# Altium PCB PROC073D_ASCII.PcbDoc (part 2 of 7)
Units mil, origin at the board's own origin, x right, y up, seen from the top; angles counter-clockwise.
Board outline 2165.35 x 2695.12 mil, 8 copper layers (Top Layer, L2_GND, L3_SIGNAL 1, L4_SIGNAL 2, L5_SIGNAL 3, L6_SIGNAL 4, L7_GND, Bottom Layer), stack 56.1 mil thick; 414 components, 319 nets, 1353 pads, 1669 vias.
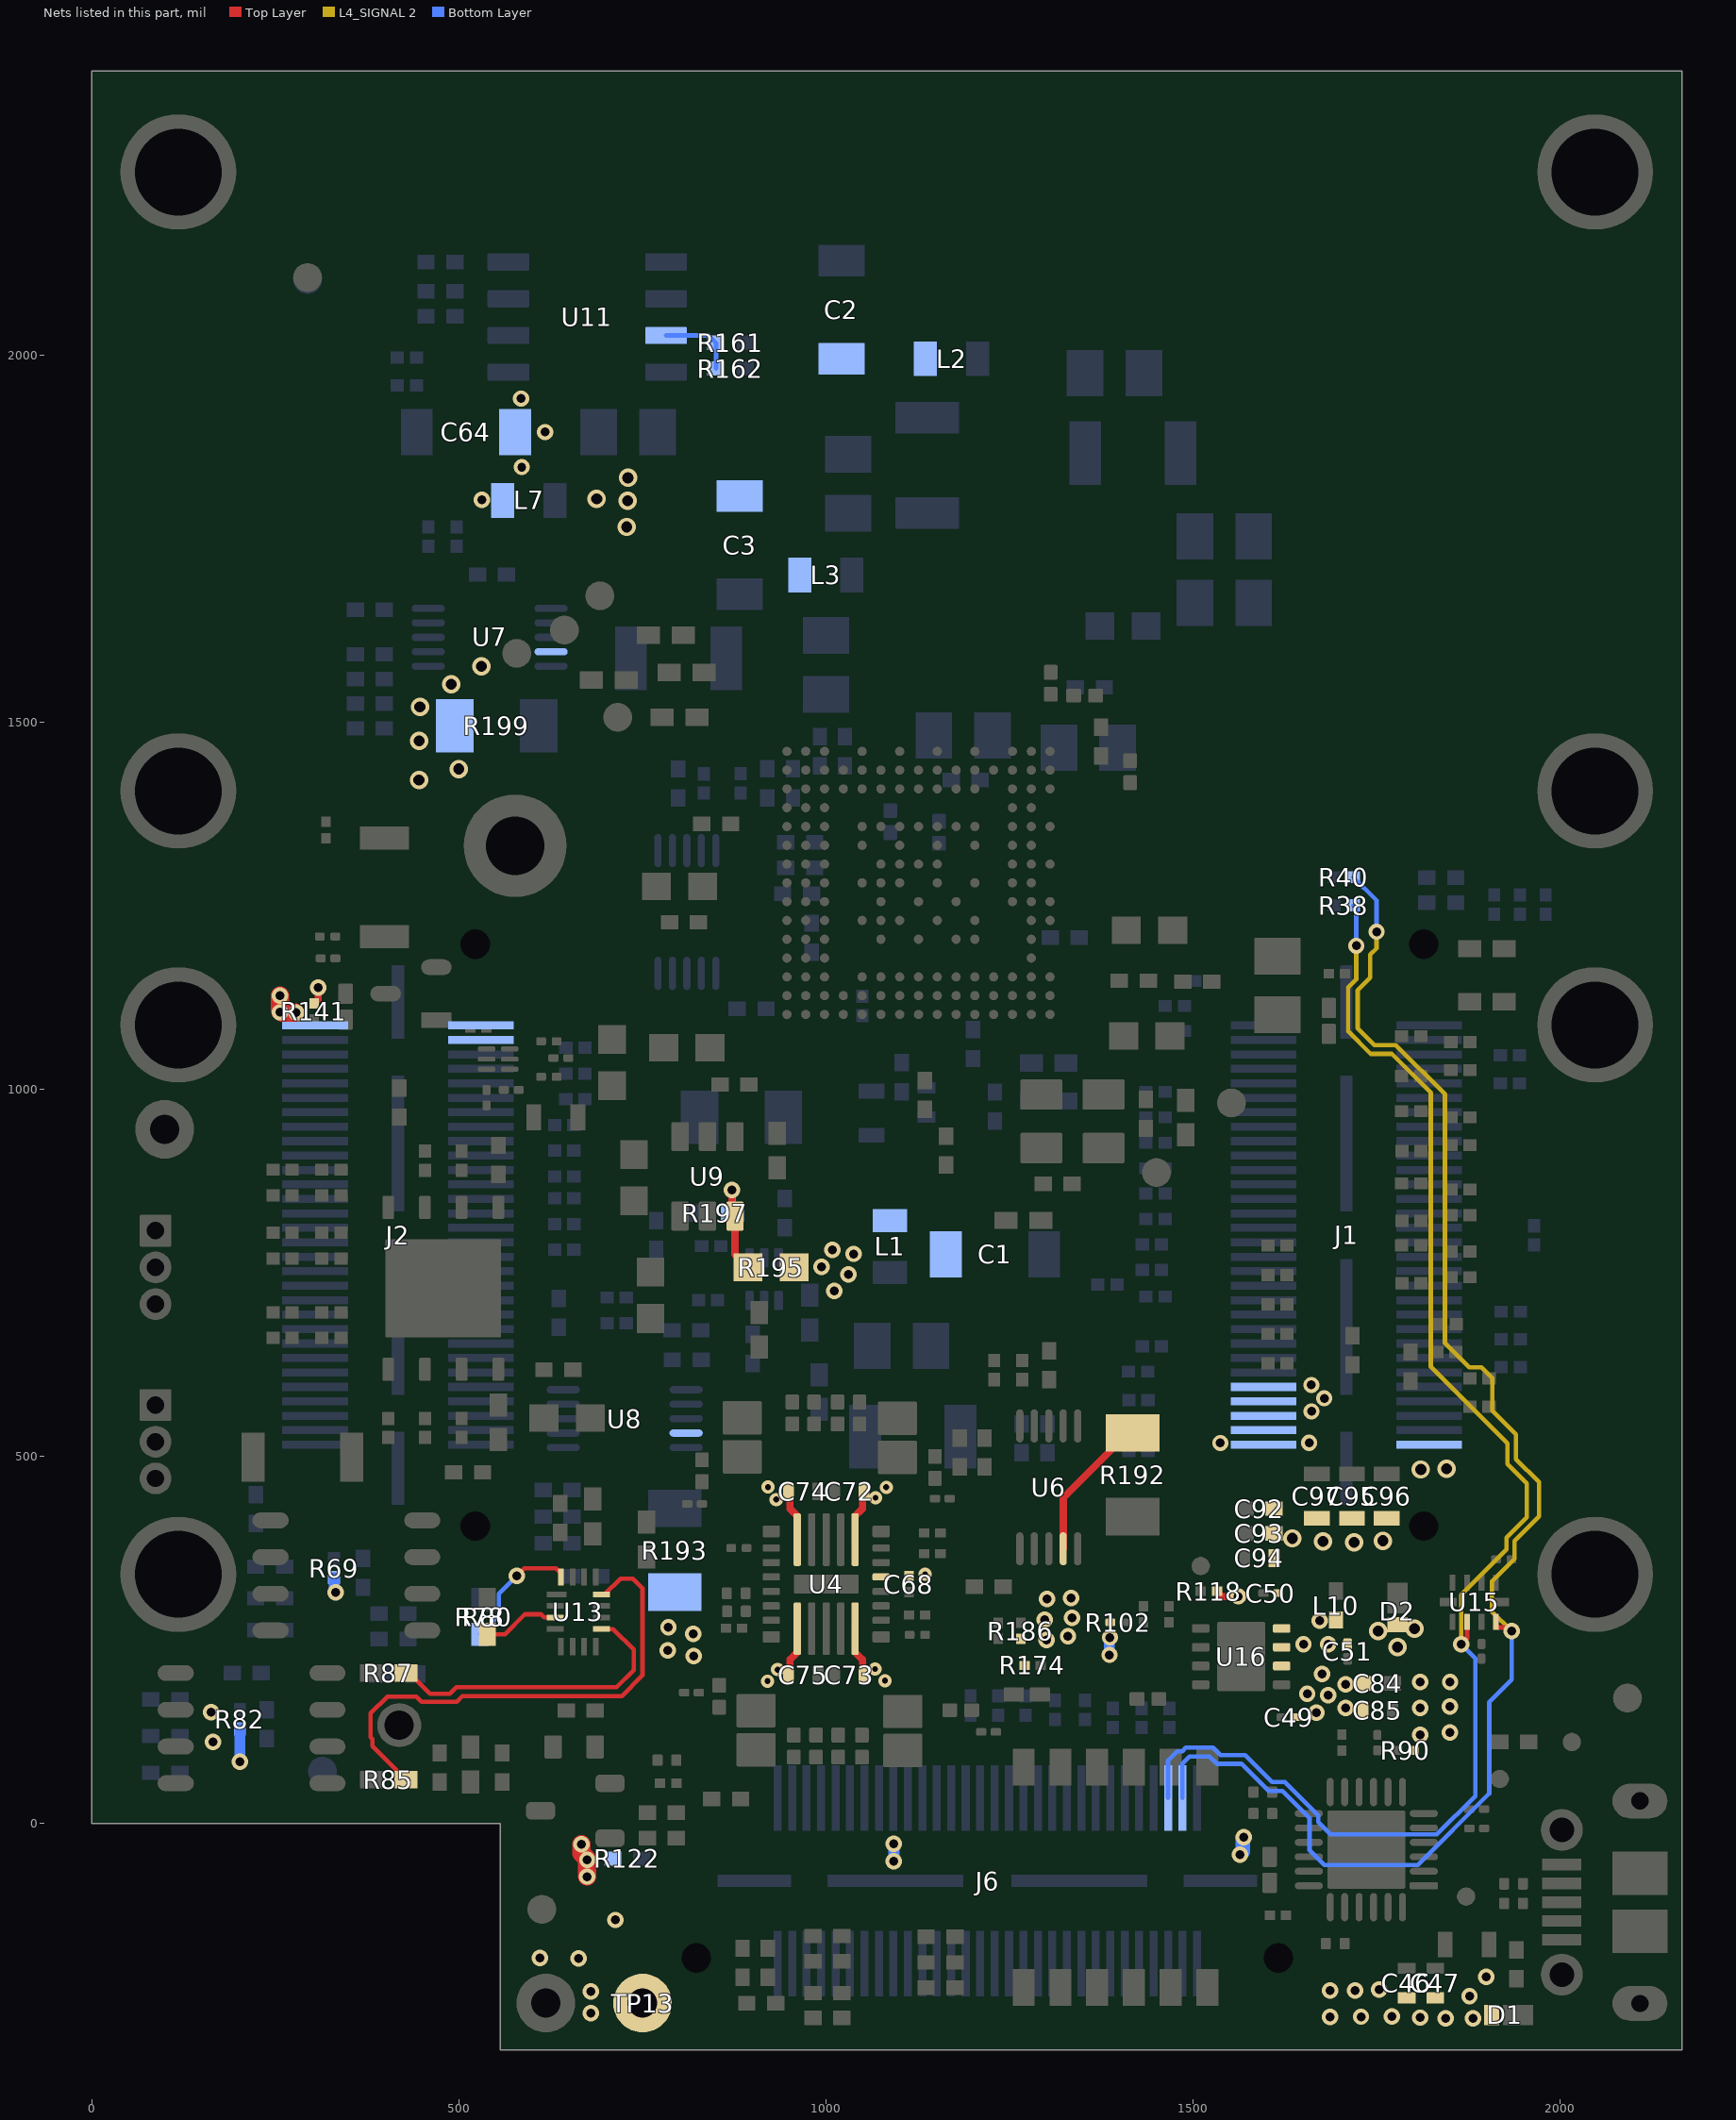
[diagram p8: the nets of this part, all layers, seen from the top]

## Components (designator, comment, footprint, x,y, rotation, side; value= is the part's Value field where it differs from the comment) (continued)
R152 "CRCW040210K0FKED" 0402L 1795.94,622.55 r90 top
R153 "CRCW0402100KFKED" 0402L 1837.89,1288.13 r0 bottom
R154 "CRCW0402100KFKED" 0402L 1837.89,1254.19 r0 bottom
R155 "CRCW0402100KFKED" 0402L 1717.01,644.6 r90 top
R156 "CRCW0402100KFKED" 0402L 1230,976.43 r90 bottom
R157 "CRCW040210K0FKED" 0402L 475,2052.43 r180 bottom
R158 "CRCW040210K0FKED" 0402L 475,2086.43 r0 bottom
R159 "CRCW02010000Z0ED" 0201 429.4,1996.15 r180 bottom
R160 "CRCW02010000Z0ED" 0201 429.4,1958.61 r180 bottom
R161 "CRCW040210K0FKED" 0402L 870,2016.43 r0 bottom
R162 "CRCW040210K0FKED" 0402L 870,1981.43 r180 bottom
R163 "CRCW020120R0FNED" 0201_033 1271.67,160.87 r270 bottom
R164 "CRCW020120R0FNED" 0201_033 1311.95,154.88 r270 bottom
R165 "RR0306P-103-D" FP-RR0306P-103-D_0201-IPC_C 537.82,988.59 r270 top
R166 "CRCW020120R0FNED" 0201_033 1352.68,154.88 r270 bottom
R167 "CRCW020120R0FNED" 0201_033 1390.77,144.03 r270 bottom
R168 "CRCW020120R0FNED" 0201_033 1429.92,144.03 r270 bottom
R169 "CRCW040210K0JNED" 0402 1900,1191.43 r180 top
R170 "CRCW020120R0FNED" 0201_033 1467.83,144.03 r270 bottom
R171 "RC0201JR-07510RL" 0201L 526.8,1083.65 r180 top
R172 "ERJ-2GEJ511X" 0402L 665.93,154.18 r180 top
R173 "RC0402FR-073R83L" "FP-RC0402FR-073R83L_0402 (1005 Metric)-IPC_C" 854.61,173.45 r270 top
R174 "RC0201JR-07510RL" 0201L 1281.31,215.41 r0 top
R175 "RC0402FR-073R83L" "FP-RC0402FR-073R83L_0402 (1005 Metric)-IPC_C" 1183.51,154.63 r180 top
R176 "RC0201FR-074K99L" 0201L 1123.96,284.16 r0 top
R177 "RC0201FR-074K99L" 0201L 1144.8,367.66 r0 top
R178 "RC0402FR-073R83L" "FP-RC0402FR-073R83L_0402 (1005 Metric)-IPC_C" 831.12,480.54 r90 top
R179 "ERJ-2GEJ511X" 0402L 776.61,-19.74 r180 top
R180 "RC0201JR-070RL" "FP-RC0201JR-070RL_0201 (0603 Metric)-MFG" 878.14,289.16 r0 top
R181 "RC0201JR-070RL" "FP-RC0201JR-070RL_0201 (0603 Metric)-MFG" 877.8,313.66 r0 top
R182 "CRCW0402100KFKED" 0402L 776.61,14.84 r0 top
R183 "RC0402FR-073R83L" "FP-RC0402FR-073R83L_0402 (1005 Metric)-IPC_C" 1148.43,485.13 r90 top
R184 "CRCW040210K0JNED" 0402 1303.12,984.02 r180 bottom
R185 "CRCW04020000Z0ED" 0402 1303.12,1035.79 r180 bottom
R186 "RC0201JR-071KL" 0201L 1265.29,262.61 r270 top
R187 "RC0201FR-074K99L" 0201L 1144.8,396.01 r0 top
R188 "RC0201FR-074K99L" 0201L 874.94,266.16 r180 top
R189 "RR0306P-103-D" FP-RR0306P-103-D_0201-IPC_C 1124.42,257.16 r0 top
R190 "RR0306P-103-D" FP-RR0306P-103-D_0201-IPC_C 881.46,375.35 r180 top
R191 "RCS06030000Z0EA" 0603 738.67,879.58 r90 top
R192 "PMR18EZPFV2L00" 1206 1417.66,475.04 r90 top
R193 "PMR18EZPFV2L00" 1206 794.24,372.27 r270 bottom
R194 "RC0201FR-071K96L" 0201L 1234.41,262.61 r90 top
R195 "MCT06030Z0000ZP500" 0603 925.25,757.58 r180 top
R196 "CRCW0402510RJNED" 0402 908.98,672.41 r90 top
R197 "ERJ-2RKF1003X" 0402 848.74,831.43 r0 bottom
R198 "RC0201JR-070RL" "FP-RC0201JR-070RL_0201 (0603 Metric)-MFG" 783.5,86.51 r180 top
R199 "PMR18EZPFV2L00" 1206 551.66,1495.08 r180 bottom
R200 "PMR18EZPFV2L00" 1206 884.81,961.78 r0 bottom
R201 "CRCW0201100KFKED" 0201L 785.2,55.06 r0 top
R202 "ERJ-2GE0R00X" 0402L 911.88,-244.3 r180 top
R203 "CRCW040210K0FKED" 0402L 1002.05,-230.73 r0 top
R204 "CRCW04027K87FKED" 0402L 1155.98,-223.19 r0 top
R205 "CRCW040282K5FKED" 0402L 1002.05,-264.45 r0 top
R206 "CRCW040210K0FKED" 0402L 920.56,-189.36 r270 top
R207 "CRCW04027K87FKED" 0402L 1155.98,-188.88 r0 top
R208 "CRCW040282K5FKED" 0402L 886.26,-189.36 r270 top
R209 "CRCW040210K0FKED" 0402L 1002.05,-152.92 r0 top
R210 "CRCW04027K87FKED" 0402L 1155.98,-153.92 r0 top
R211 "CRCW040282K5FKED" 0402L 1002.05,-187.4 r0 top
R212 "RC0201JR-07220RL" 0201L 1695.76,1157.61 r0 top
R213 "RC0201JR-07220RL" 0201L 319.32,1352.92 r90 top
R214 "RC0201JR-070RL" "FP-RC0201JR-070RL_0201 (0603 Metric)-IPC_C" 321.89,1178.31 r180 top
R215 "RR0306P-103-D" FP-RR0306P-103-D_0201-IPC_C 321.39,1208.04 r0 top
R216 "ERJ-2GE0R00X" 0402 516.22,80.59 r90 top
R217 "CRCW02010000Z0ED" 0201_Silk 326.6,890.5 r180 top
R218 "CRCW02010000Z0ED" 0201_Silk 326.6,855.5 r180 top
R219 "CRCW02010000Z0ED" 0201_Silk 1797.27,736.22 r0 top
R220 "CRCW02010000Z0ED" 0201_Silk 1796.85,787.38 r0 top
R221 "CRCW02010000Z0ED" 0201_Silk 326.6,804.68 r180 top
R222 "CRCW02010000Z0ED" 0201_Silk 326.6,769.68 r180 top
R223 "CRCW02010000Z0ED" 0201_Silk 326.6,696.43 r180 top
R224 "CRCW02010000Z0ED" 0201_Silk 326.6,661.43 r180 top
R225 "CRCW02010000Z0ED" 0201_Silk 1797.27,820.68 r0 top
R226 "CRCW02010000Z0ED" 0201_Silk 1796.85,871.84 r0 top
R227 "CRCW02010000Z0ED" 0201_Silk 1797.27,916.04 r0 top
R228 "CRCW02010000Z0ED" 0201_Silk 1796.85,970.18 r0 top
R229 "CRCW02010000Z0ED" 0201_Silk 1796.85,1017.88 r0 top
R230 "CRCW02010000Z0ED" 0201_Silk 1796.85,1072.37 r0 top
S1 "218-6LPST" SW_218-6LPST 1394.21,-73.19 r90 top locked
S2 "B3U-1000P" SW_B3U-1000P 287.11,498.89 r0 top
S3 "B3U-1000P" SW_B3U-1000P 398.63,1274.97 r90 top
TP1 "TESTPOINT" TP_25MIL-SMT 1871.57,-99.27 r270 top
TP2 "TP_SM_1MM" TP_SM_1MM 692.27,1671.93 r90 top
TP3 "TP_SM_1MM" TP_SM_1MM 643.74,1625.33 r90 top
TP4 "TP_SM_1MM" TP_SM_1MM 716.44,1506.43 r90 top
TP5 "TP_SM_1MM" TP_SM_1MM 578.94,1593.59 r90 top
TP6 "TP_SM_1MM" TP_SM_1MM 1552,981.43 r90 top
TP7 "TP_SM_1MM" TP_SM_1MM 1450,886.43 r90 top
TP8 "TESTPOINT" TP_25MIL-SMT 1510.32,350.86 r180 top
TP9 "TESTPOINT" TP_25MIL-SMT 2015.61,111.24 r0 top
TP10 "TESTPOINT" TP_25MIL-SMT 1917.5,60.89 r90 top
TP11 "TESTPOINT" TP_VIA_060RND040 418.88,134.12 r180 top
TP12 "5001" Keystone5001 618.57,-244.3 r0 top
TP13 "5001" Keystone5001 750.27,-244.3 r0 top
TP14 "5001" Keystone5001 99.51,945.49 r0 top
U1 "IWR6843QAGABL" ABL0161B 1125.98,1281.05 r270 top locked
U2 "MX25V1635FZNQ" WSON-8L_6x5MM_EP 478.88,728.85 r270 top
U3 "TMP112AQDRLRQ1" DRL0006A 915.74,741.43 r270 bottom
U4 "LP87524JRNFRQ1" RNF0026C 1000.33,326.14 r0 top
U5 "TCAN1042HGVDQ1" D0008A_L 347.08,338.05 r180 top
U6 "INA226AIDGST" DGS0010A_L 1303.36,457.93 r270 top
U7 "INA226AIDGST" DGS0010A_L 542.07,1615.4 r0 bottom
U8 "INA226AIDGST" DGS0010A_L 725.86,551.56 r0 bottom
U9 "TPS22917DBVR" DBV0006A_N 838.74,881.43 r90 top
U10 "INA226AIDGST" DGS0010A_L 810.59,1241.43 r270 bottom
U11 "CAT24C08WI-GT3" SOIC-8 675,2051.43 r180 bottom
U12 "TCAN1042HGVDQ1" D0008A_L 217.94,130.08 r180 top
U13 "TS3A5018RSVR" RSV0016A 662.79,288.61 r0 top
U14 "CP2105-F01-GMR" FP-CP2105-F01-GMR_QFN24-EP-IPC_A 1735.81,-35.3 r180 top
U15 "TS5A23157RSER" RSE0010A 1882.76,301.64 r270 top
U16 "TPS2115ADRBR" DRB0008B 1565.35,227.53 r0 top
U17 "SN74LVC1G11DSFR" DSF0006A 553.57,1041.14 r180 top
Y1 "CX3225SA40000D0PTWCC" Kyocera_CX3225SA 1335.59,956.43 r90 top
ZZ1 "This Assembly Note is for PCB labels only" AssemblyNoteLabel -833.57,3288.93 r0 top
ZZ2 "These assemblies are ESD sensitive, ESD precautions shall be observed." AssemblyNote -831.16,3211.77 r0 top
ZZ3 "These assemblies must be clean and free from flux and all contaminants. Use of no clean flux is not acceptable." AssemblyNote -831.16,3124.96 r0 top
ZZ4 "These assemblies must comply with workmanship standards IPC-A-610 Class 2, unless otherwise specified." AssemblyNote -835.98,3033.33 r0 top
ZZ5 "INDICATION FOR COMPONENTS D* ARE GIVEN AT THEIR CATHODE SIDE." AssemblyNote -834.59,2945.73 r0 top

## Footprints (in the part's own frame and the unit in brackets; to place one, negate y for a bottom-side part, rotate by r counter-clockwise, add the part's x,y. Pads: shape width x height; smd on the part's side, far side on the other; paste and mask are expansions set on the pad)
0201 [mm] "Data from Kemet datasheet CC101_COM dated 7/28/11"
  rect 0.46x0.42 smd mask+0: 1(-0.33,0) 2(0.33,0)
0201_033 [mm] "SMD, 2-Leads, Height 0.33mm"
  rect 0.46x0.42 smd mask+0: 1(-0.33,0) 2(0.33,0)
0201_033L [mm] "0201"
  rect 0.36x0.32 smd mask+0: 1(-0.28,0) 2(0.28,0)
0201_Silk [mm] "Data from Kemet datasheet CC101_COM dated 7/28/11"
  rect 0.46x0.42 smd mask+0: 1(-0.33,0) 2(0.33,0)
  silkscreen extent -0.75,-0.4 0.75,0.4
0201L [mm] "Data from Kemet datasheet CC101_COM dated 7/28/11"
  rect 0.36x0.32 smd mask+0: 1(-0.28,0) 2(0.28,0)
0402 [mm] "0402 from SM-752 data"
  rect 0.8x0.6 smd: 1(-0.6,0) 2(0.6,0)
  silkscreen extent -1.22,-0.52 1.22,0.52
0402_070 [mil] "SMD, 2-Leads, Body 1.2x0.7mm, Height 0.7mm"
  rect 15x24 smd: 1(-20,0) 2(20,0)
0402L [mm] "0402 from SM-752 data"
  rect 0.6x0.5 smd: 1(-0.5,0) 2(0.5,0)
0402S [mil] "Based on C0402S footprint from PADS legacy"
  rect 15x24 smd: 1(-20,0) 2(20,0)
0603 [mm] "0603 from SM-752 data"
  rect 1x0.95 smd: 1(-0.8,0) 2(0.8,0)
  silkscreen extent -1.52,-0.69 1.52,0.69
0603S [mil]
  rect 20x35 smd: 1(-30,0) 2(30,0)
  silkscreen extent -10,-17 10,17
0805_HV [mil] "0805 with 30mil clearance between pads"
  rect 50x63 smd: 1(-40,0) 2(40,0)
  silkscreen extent -74,-40 74,40
1206 [mm] "1206 from SM-752 data"
  rect 1.3x1.85 smd: 1(-1.45,0) 2(1.45,0)
  silkscreen extent -2.4,-1.21 2.4,1.21
1206_180 [mm] "1206_180"
  rect 1.1x1.6 smd: 1(-1.7,0) 2(1.7,0)
  silkscreen extent -0.9,-1 0.9,1
1210_280 [mm] "SMD, 2-Leads, Body 3.6x2.8mm, Height 2.8mm"
  rect 1.1x2.2 smd: 1(-1.65,0) 2(1.65,0)
  silkscreen extent -0.84,-1.4 0.84,1.4
ABL0161B [mm] "BGA, 161-Balls, Body 10.4x10.4mm, Pitch 0.65mm"
  round 0.32 smd: A1(-4.55,4.55) A2(-3.9,4.55) A3(-3.25,4.55) A5(-1.95,4.55) A7(-0.65,4.55) A9(0.65,4.55) A10(1.3,4.55) A13(3.25,4.55) A14(3.9,4.55) A15(4.55,4.55) B1(-4.55,3.9) B2(-3.9,3.9) B3(-3.25,3.9) B4(-2.6,3.9) B5(-1.95,3.9) B6(-1.3,3.9) B7(-0.65,3.9) B8(0,3.9) B9(0.65,3.9) B10(1.3,3.9) B11(1.95,3.9) B12(2.6,3.9) B13(3.25,3.9) B14(3.9,3.9) B15(4.55,3.9) C1(-4.55,3.25) C2(-3.9,3.25) C3(-3.25,3.25) C4(-2.6,3.25) C5(-1.95,3.25) C6(-1.3,3.25) C7(-0.65,3.25) C8(0,3.25) C9(0.65,3.25) C13(3.25,3.25) C14(3.9,3.25) C15(4.55,3.25) D2(-3.9,2.6) D13(3.25,2.6) D14(3.9,2.6) D15(4.55,2.6) E1(-4.55,1.95) E2(-3.9,1.95) E3(-3.25,1.95) E5(-1.95,1.95) E6(-1.3,1.95) E8(0,1.95) E10(1.3,1.95) E11(1.95,1.95) E13(3.25,1.95) E14(3.9,1.95) E15(4.55,1.95) F2(-3.9,1.3) F3(-3.25,1.3) F5(-1.95,1.3) F9(0.65,1.3) F11(1.95,1.3) F13(3.25,1.3) F14(3.9,1.3) F15(4.55,1.3) G1(-4.55,0.65) G2(-3.9,0.65) G3(-3.25,0.65) G5(-1.95,0.65) G6(-1.3,0.65) G7(-0.65,0.65) G8(0,0.65) G10(1.3,0.65) G13(3.25,0.65) G14(3.9,0.65) G15(4.55,0.65) H2(-3.9,0) H3(-3.25,0) H5(-1.95,0) H7(-0.65,0) H9(0.65,0) H11(1.95,0) H13(3.25,0) H14(3.9,0) H15(4.55,0) J1(-4.55,-0.65) J2(-3.9,-0.65) J3(-3.25,-0.65) J5(-1.95,-0.65) J6(-1.3,-0.65) J7(-0.65,-0.65) J8(0,-0.65) J10(1.3,-0.65) J13(3.25,-0.65) J14(3.9,-0.65) J15(4.55,-0.65) K2(-3.9,-1.3) K3(-3.25,-1.3) K5(-1.95,-1.3) K7(-0.65,-1.3) K8(0,-1.3) K9(0.65,-1.3) K10(1.3,-1.3) K11(1.95,-1.3) K13(3.25,-1.3) K14(3.9,-1.3) K15(4.55,-1.3) L1(-4.55,-1.95) L2(-3.9,-1.95) L3(-3.25,-1.95) L5(-1.95,-1.95) L6(-1.3,-1.95) L8(0,-1.95) L10(1.3,-1.95) L13(3.25,-1.95) L14(3.9,-1.95) L15(4.55,-1.95) M2(-3.9,-2.6) M3(-3.25,-2.6) M14(3.9,-2.6) M15(4.55,-2.6) N1(-4.55,-3.25) N2(-3.9,-3.25) N3(-3.25,-3.25) N4(-2.6,-3.25) N5(-1.95,-3.25) N6(-1.3,-3.25) N7(-0.65,-3.25) N8(0,-3.25) N9(0.65,-3.25) N10(1.3,-3.25) N11(1.95,-3.25) N12(2.6,-3.25) N13(3.25,-3.25) N14(3.9,-3.25) N15(4.55,-3.25) P1(-4.55,-3.9) P2(-3.9,-3.9) P3(-3.25,-3.9) P4(-2.6,-3.9) P5(-1.95,-3.9) P6(-1.3,-3.9) P7(-0.65,-3.9) P8(0,-3.9) P9(0.65,-3.9) P10(1.3,-3.9) P11(1.95,-3.9) P12(2.6,-3.9) P13(3.25,-3.9) P14(3.9,-3.9) P15(4.55,-3.9) R1(-4.55,-4.55) R2(-3.9,-4.55) R3(-3.25,-4.55) R4(-2.6,-4.55) R5(-1.95,-4.55) R6(-1.3,-4.55) R7(-0.65,-4.55) R8(0,-4.55) R9(0.65,-4.55) R10(1.3,-4.55) R11(1.95,-4.55) R12(2.6,-4.55) R13(3.25,-4.55) R14(3.9,-4.55) R15(4.55,-4.55)
  silkscreen extent -5.3,-5.3 5.3,5.3
APHHS1005_Green [mm] "SMD, 2-Leads, Body 1x0.5mm"
  rrect20% 0.7x0.5 smd: 1(-0.45,0) 2(0.45,0)
  silkscreen extent -0.8,-0.65 1.2,0.65
AssemblyNote [mil] "Assembly Note"
AssemblyNoteLabel [mil] "Assembly Note for PCB Labels"
CE_Mark_5mm [mil] "Minimum text height for CE Mark"
CONN_105017-0001 [mm] "Molex Micro USB-B"
  rect 0.4x1.35 smd: 1(-1.3,1.35) 2(-0.65,1.35) 3(0,1.35) 4(0.65,1.35) 5(1.3,1.35)
  oval 1.2x1.9 hole 0.6 slot 1.3 at 90 deg: 6(-3.5,-1.35) 9(3.5,-1.35)
  rect 1.5x1.9 smd: 7(-1,-1.35) 8(1,-1.35)
  round 1.45 hole 0.85: 10(2.5,1.35) 11(-2.5,1.35)
  Top Layer region: 3.499,-0.399 2.299,-0.399 2.299,-2.299 3.499,-2.299
  Top Layer region: -3.5,-2.299 -2.3,-2.299 -2.3,-0.399 -3.5,-0.399
  silkscreen extent -4.1,-0.2 4.1,1.4
D0008A_L [mm] "SOIC, 8-Leads, Body 4.9x3.9mm, Pitch 1.27mm, IPC High Density"
  oval 1.25x0.55 smd: 1(-2.625,1.905) 2(-2.625,0.635) 3(-2.625,-0.635) 4(-2.625,-1.905) 5(2.625,-1.905) 6(2.625,-0.635) 7(2.625,0.635) 8(2.625,1.905)
  silkscreen extent -3.1,-2.5 0.9,2.5
DBV0006A_N [mm] "SOT23, 6-Leads, Body 2.9x1.6mm, Pitch 0.95mm, Lead Span 2.8mm, IPC Medium Density"
  rrect17% 1x0.6 smd: 1(-1.375,0.95) 2(-1.375,0) 3(-1.375,-0.95) 4(1.375,-0.95) 5(1.375,0) 6(1.375,0.95)
  silkscreen extent -1.68,-1.55 0.5,1.55
DGS0010A_L [mm] "TSSOP, 10-Leads, Body 3x3mm, Pitch 0.5mm, IPC High Density"
  oval 1.15x0.25 smd: 1(-2.125,1) 2(-2.125,0.5) 3(-2.125,0) 4(-2.125,-0.5) 5(-2.125,-1) 6(2.125,-1) 7(2.125,-0.5) 8(2.125,0) 9(2.125,0.5) 10(2.125,1)
  silkscreen extent -2.65,-1.55 0.9,1.55
DRB0008B [mm] "SON, 8-Leads, Body 3x3mm, Pitch 0.65mm, Thermal Pad 2.4x1.65mm, TI Recommended"
  rrect33% 0.6x0.3 smd: 1(-1.4,0.975) 2(-1.4,0.325) 3(-1.4,-0.325) 4(-1.4,-0.975) 5(1.4,-0.975) 6(1.4,-0.325) 7(1.4,0.325) 8(1.4,0.975)
  rrect9% 1.47x1.06 on Top Paste: 9(0,-0.63) 9(0,0.63)
  rrect6% 1.65x2.4 smd paste-1.2: 9(0,0)
  silkscreen extent -1.73,-1.73 1.73,1.73
DRL0006A [mm] "SOTFL, 6-Flat Leads, Body 1.2x1.6x0.6mm, Pitch 0.5mm, TI recommended"
  rrect33% 0.67x0.3 smd: 1(-0.74,0.5) 2(-0.74,0) 3(-0.74,-0.5) 4(0.74,-0.5) 5(0.74,0) 6(0.74,0.5)
  silkscreen extent -0.9,-0.95 0.5,0.95
DSF0006A [mm] "TI recommended land pattern"
  rrect59% 0.6x0.17 smd mask+0: 1(-0.4,0.35) 2(-0.4,0) 3(-0.4,-0.35) 4(0.4,-0.35) 5(0.4,0) 6(0.4,0.35)
  silkscreen extent -0.6,-0.63 0.6,0.63
DSN2_0603 [mm] "SMD, 2-Leads, Body 1.6x0.8mm"
  rect 0.52x0.7 smd: 1(-0.64,0)
  rect 1.05x0.7 smd: 2(0.275,0)
  silkscreen extent -1.4,-0.75 0.8,0.75
FCC_disclaimer [mil]
Fiducial10-20 [mm]
  round 1 smd mask+0: 1(0,0)
  Top Layer keep-out circle w1.178: c0,0 r0.5
FP-BSS123-7-F_SOT23-IPC_C [mm]
  rrect18% 1.059x0.547 smd paste+0 mask+0: 1(-0.877,0.915)
  rrect100% 1.059x0.547 smd paste+0 mask+0: 2(-0.877,-0.915) 3(0.877,0)
FP-CL03A105MO3NRNH_0201-IPC_C [mil]
  rrect33% 15.83x11.94 smd paste+0 mask+0: 1(-9.87,0) 2(9.87,0)
"FP-CL05A226MQ5N6J8_0402 (1005 Metric)-IPC_C" [mil]
  rrect21% 20.29x18.6 smd paste+0 mask+0: 1(-14.9,0) 2(14.9,0)
FP-CP2105-F01-GMR_QFN24-EP-IPC_A [mm]
  rrect42% 0.979x0.239 smd paste+0 mask+0: 1(-1.99,1.25)
  rrect100% 0.979x0.239 smd paste+0 mask+0: 2(-1.99,0.75) 3(-1.99,0.25) 4(-1.99,-0.25) 5(-1.99,-0.75) 6(-1.99,-1.25) 13(1.99,-1.25) 14(1.99,-0.75) 15(1.99,-0.25) 16(1.99,0.25) 17(1.99,0.75) 18(1.99,1.25)
  rrect100% 0.239x0.979 smd paste+0 mask+0: 7(-1.25,-1.99) 8(-0.75,-1.99) 9(-0.25,-1.99) 10(0.25,-1.99) 11(0.75,-1.99) 12(1.25,-1.99) 19(1.25,1.99) 20(0.75,1.99) 21(0.25,1.99) 22(-0.25,1.99) 23(-0.75,1.99) 24(-1.25,1.99)
  rrect4% 2.7x2.7 smd paste-1000 mask+0: 25(0,0)
FP-CRCW0402200RFKEDHP_0402-IPC_C [mil]
  rrect21% 20.29x18.6 smd paste+0 mask+0: 1(-14.9,0) 2(14.9,0)
"FP-GRM033R6YA104KE14D_0201 (0603 Metric)-IPC_C" [mil]
  rrect38% 13.94x10.34 smd paste+0 mask+0: 1(-10.01,0) 2(10.01,0)
FP-M50-3930342_HDR3-MFG [mm]
  rrect9% 1.1x1.1 hole 0.6 paste-1000 mask+0: 1(-1.27,1)
  round 1.1 hole 0.6 paste-1000 mask+0: 2(0,1) 3(1.27,1)
  silkscreen extent -2.97,-0.6 2.15,1.12
"FP-MCKK2012TR47M_0805 (2012 Metric)-IPC_C" [mil]
  rrect9% 45.45x53.39 smd paste+0 mask+0: 1(-26.61,0) 2(26.61,0)
"FP-RC0201JR-070RL_0201 (0603 Metric)-IPC_C" [mil]
  rrect38% 13.94x10.34 smd paste+0 mask+0: 1(-10.01,0) 2(10.01,0)
"FP-RC0201JR-070RL_0201 (0603 Metric)-MFG" [mm]
  rrect29% 0.35x0.4 smd paste+0 mask+0: 1(-0.325,0) 2(0.325,0)
"FP-RC0402FR-073R83L_0402 (1005 Metric)-IPC_C" [mil]
  rrect21% 20.29x18.6 smd paste+0 mask+0: 1(-14.9,0) 2(14.9,0)
FP-RR0306P-103-D_0201-IPC_C [mil]
  rrect37% 13.31x10.73 smd paste+0 mask+0: 1(-10.52,0) 2(10.52,0)
"FP-TMK063CG391JT-F_0201 (0603 Metric)-IPC_C" [mil]
  rrect38% 13.94x10.34 smd paste+0 mask+0: 1(-10.01,0) 2(10.01,0)
IEC_HotSurface_Small [mil]
  silkscreen extent -107,-93 107,92
Keystone5001 [mil] "For Keystone 500x miniature loop terminals"
  round 80 hole 40: 1(0,0)
  silkscreen extent -52,-52 52,52
Kyocera_CX3225SA [mm] "SMD, 4-Leads, Body 3.2x2.5mm"
  rrect10% 1.05x1.45 smd: 1(-0.925,1.075) 2(-0.925,-1.075) 3(0.925,-1.075) 4(0.925,1.075)
  silkscreen extent -1,2.28 -0.87,2.4
Label_650x200 [mil] "Thermal Transfer Label"
  round 1 on Mech13: 0(0,0)
  silkscreen extent -325,-100 325,100
MPZ2012 [mm] "TDK"
  rect 0.8x1.2 smd: 1(-0.9,0) 2(0.9,0)
RNF0026C [mm] "QFN, 26-Leads, Body 4x4.5mm, Pitch 0.5mm"
  rrect25% 0.6x0.4 smd paste-0.3: 1(-1.9,1.825) 8(-1.9,-1.825) 14(1.9,-1.825) 21(1.9,1.825)
  rrect40% 0.6x0.25 smd paste+0: 2(-1.9,1.25) 3(-1.9,0.75) 4(-1.9,0.25) 5(-1.9,-0.25) 6(-1.9,-0.75) 7(-1.9,-1.25) 15(1.9,-1.25) 16(1.9,-0.75) 17(1.9,-0.25) 18(1.9,0.25) 19(1.9,0.75) 20(1.9,1.25)
  rrect40% 0.25x1.82 smd paste-1: 9(-1,-1.54) 10(-0.5,-1.54) 11(0,-1.54) 12(0.5,-1.54) 13(1,-1.54) 22(1,1.54) 23(0.5,1.54) 24(0,1.54) 25(-0.5,1.54) 26(-1,1.54)
  rrect15% 2.24x0.66 smd paste-1: 27(0,0)
  rrect33% 0.6x0.3 on Top Paste: ""(-1.9,-1.775) ""(-1.9,1.775) ""(1.9,-1.775) ""(1.9,1.775)
  rrect33% 0.3x0.825 on Top Paste: ""(-1.575,-2.037) ""(-1.575,2.037) ""(1.575,-2.037) ""(1.575,2.037)
  rrect40% 0.25x0.81 on Top Paste: ""(-1,2.045) ""(-1,-2.045) ""(-1,-1.035) ""(-1,1.035) ""(-0.5,2.045) ""(-0.5,-2.045) ""(-0.5,-1.035) ""(-0.5,1.035) ""(0,1.035) ""(0,-2.045) ""(0,-1.035) ""(0,2.045) ""(0.5,-2.045) ""(0.5,-1.035) ""(0.5,2.045) ""(0.5,1.035) ""(1,-2.045) ""(1,-1.035) ""(1,1.035) ""(1,2.045)
  rrect15% 0.98x0.66 on Top Paste: ""(-0.59,0) ""(0.59,0)
  silkscreen extent -2.45,-2.7 2.45,2.7
RSE0010A [mm] "QFN, 10-Leads, Body 1.5x2mm, Pitch 0.5mm, TI Recommended"
  rect 0.55x0.2 smd: 1(-0.675,0.75) 2(-0.675,0.25) 3(-0.675,-0.25) 4(-0.675,-0.75) 6(0.675,-0.75) 7(0.675,-0.25) 8(0.675,0.25) 9(0.675,0.75)
  rect 0.3x0.6 smd: 5(0,-0.9) 10(0,0.9)
  silkscreen extent -1.07,-1.18 0.78,1.18
RSV0016A [mm] "QFN, 16-Leads, Body 1.8x2.6mm, Pitch 0.4mm, TI Recommended"
  rect 0.7x0.2 smd: 1(-0.75,0.6)
  rect 0.6x0.2 smd: 2(-0.8,0.2) 3(-0.8,-0.2) 4(-0.8,-0.6) 9(0.8,-0.6) 10(0.8,-0.2) 11(0.8,0.2) 12(0.8,0.6)
  rect 0.2x0.6 smd: 5(-0.6,-1.2) 6(-0.2,-1.2) 7(0.2,-1.2) 8(0.6,-1.2) 13(0.6,1.2) 14(0.2,1.2) 15(-0.2,1.2) 16(-0.6,1.2)
  silkscreen extent -1.08,-1.33 1.08,1.45
Samtec_QSH-030-01-X-D-A [mm] "Receptacle, 0.5 mm, 30x2, TH"
  rect 2.27x0.279 smd: 1(-2.865,7.25) 2(2.865,7.25) 3(-2.865,6.75) 4(2.865,6.75) 5(-2.865,6.25) 6(2.865,6.25) 7(-2.865,5.75) 8(2.865,5.75) 9(-2.865,5.25) 10(2.865,5.25) 11(-2.865,4.75) 12(2.865,4.75) 13(-2.865,4.25) 14(2.865,4.25) 15(-2.865,3.75) 16(2.865,3.75) 17(-2.865,3.25) 18(2.865,3.25) 19(-2.865,2.75) 20(2.865,2.75) 21(-2.865,2.25) 22(2.865,2.25) 23(-2.865,1.75) 24(2.865,1.75) 25(-2.865,1.25) 26(2.865,1.25) 27(-2.865,0.75) 28(2.865,0.75) 29(-2.865,0.25) 30(2.865,0.25) 31(-2.865,-0.25) 32(2.865,-0.25) 33(-2.865,-0.75) 34(2.865,-0.75) 35(-2.865,-1.25) 36(2.865,-1.25) 37(-2.865,-1.75) 38(2.865,-1.75) 39(-2.865,-2.25) 40(2.865,-2.25) 41(-2.865,-2.75) 42(2.865,-2.75) 43(-2.865,-3.25) 44(2.865,-3.25) 45(-2.865,-3.75) 46(2.865,-3.75) 47(-2.865,-4.25) 48(2.865,-4.25) 49(-2.865,-4.75) 50(2.865,-4.75) 51(-2.865,-5.25) 52(2.865,-5.25) 53(-2.865,-5.75) 54(2.865,-5.75) 55(-2.865,-6.25) 56(2.865,-6.25) 57(-2.865,-6.75) 58(2.865,-6.75) 59(-2.865,-7.25) 60(2.865,-7.25)
  round 0 hole 1.02 unplated mask+0: MH1(2.67,10.065) MH2(2.67,-10.065)
  rect 0.43x2.54 smd: MP1(0,8.065) MP4(0,-8.065)
  rect 0.43x4.7 smd: MP2(0,3.175) MP3(0,-3.175)
  silkscreen extent -3.9,-10.66 3.62,10.66
SOIC-8 [mm] "duplicate of SO-8.  SOIC, 8-Leads, Body 5.0x4.0mm (max), Pitch 1.27mm, IPC Medium Density"
  rrect17% 1.45x0.6 smd: 1(-2.725,1.905) 2(-2.725,0.635) 3(-2.725,-0.635) 4(-2.725,-1.905) 5(2.725,-1.905) 6(2.725,-0.635) 7(2.725,0.635) 8(2.725,1.905)
  silkscreen extent -3.5,-2.5 0.9,2.5
SOT-23 [mm] "SOT23, 3-Leads, Body 2.9x1.3mm, Pitch 0.95mm, Lead Span 2.5mm, IPC Medium Density"
  rrect50% 1x0.6 smd: 1(-1.2,0.95) 2(-1.2,-0.95) 3(1.2,0)
  silkscreen extent -1.62,-1.5 0.7,1.5
SW_218-6LPST [mm] "SMD, 12-Leads, Body 5.8x8.79mm"
  rect 1.27x0.76 smd: 1(-3.81,3.175) 2(-3.81,1.905) 3(-3.81,0.635) 4(-3.81,-0.635) 5(-3.81,-1.905) 6(-3.81,-3.175) 7(3.81,-3.175) 7(3.81,-3.175) 8(3.81,-1.905) 9(3.81,-0.635) 10(3.81,0.635) 11(3.81,1.905) 12(3.81,3.175)
  silkscreen extent -2.9,-4.4 2.9,4.7
SW_B3U-1000P [mm] "OMRON"
  rect 0.8x1.7 smd: 1(-1.7,0) 2(1.7,0)
  silkscreen extent -1.5,-1.25 1.5,1.25
TI_Stacked_Overlay_Small [mil]
TI_Symbol_Overlay_Small [mil]
TLMx1000_Yellow [mm] "SMD, 2-Leads, Body 1.6x0.8mm"
  rrect17% 0.6x0.8 smd: 1(-0.725,0) 2(0.725,0)
  silkscreen extent -0.98,-0.8 1.6,0.8
TP_25MIL-SMT [mil]
  round 25 smd mask+0: 1(0,0)
TP_SM_1MM [mm] "1mm Test Point, SMT"
  round 1 smd paste-0.5: 1(0,0)
TP_VIA_060RND040 [mil] "TP_VIA_060RND040"
  round 60 hole 40: 1(0,0)
WEEE_Minimum [mil] "WEEElie bin"
  silkscreen extent 22,-71 54,74
WSON-8L_6x5MM_EP [mm] "SMD, 8-Leads, Body 6x5mm, Pitch 1.27mm"
  rrect25% 0.8x0.4 smd: 1(-2.8,1.905) 2(-2.8,0.635) 3(-2.8,-0.635) 4(-2.8,-1.905) 5(2.8,-1.905) 6(2.8,-0.635) 7(2.8,0.635) 8(2.8,1.905)
  rrect3% 3.4x4 smd paste-3: 9(0,0)
  rrect7% 1.468x1.698 on Top Paste: ""(-0.834,0.949) ""(-0.834,-0.949) ""(0.834,0.949) ""(0.834,-0.949)
  silkscreen extent -3.2,-2.7 3.2,2.7

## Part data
C1 C2 C3 C64: library part CMP-0008770-2, "CAP, CERM, 22 uF, 6.3 V, +/- 10%, X7R, AEC-Q200 Grade 1, 1206"
C4 C5 C9 C10 C11 C12 C14 C16 C19 C20 C21 C28 C29: library part CMP-0078265-1, "CAP, CERM, 0.22 µF, 16 V,+/- 10%, X7R, AEC-Q200 Grade 1, 0402"
C6: library part CMP-0006330-2, "CAP, CERM, 0.047 uF, 50 V, +/- 10%, X7R, AEC-Q200 Grade 1, 0402"
C7 C8 C13 C15 C23 C24: library part CMP-0085348-1, "CAP, CERM, 10 µF, 10 V,+/- 20%, X7R, 0805"
C17 C27: library part CMP-0007134-5, "CAP, CERM, 2.2 uF, 6.3 V, +/- 10%, X7R, AEC-Q200 Grade 1, 0603"
C18 C22 C35: library part CMP-0007136-5, "CAP, CERM, 1 uF, 16 V, +/- 10%, X7R, AEC-Q200 Grade 1, 0603"
C25 C26: library part CMP-0006351-2, "CAP, CERM, 0.1 uF, 16 V, +/- 10%, X7R, 0402"
C30: library part CMP-0006352-2, "CAP, CERM, 0.01 uF, 25 V, +/- 10%, X7R, 0402"
C31: library part CMP-0064969-1, "CAP, CERM, 0.1 uF, 10 V,+/- 10%, X7S, 0201"
C32 C33: library part CMP-0006367-2, "CAP, CERM, 4.7 pF, 50 V, +/- 2%, C0G/NP0, 0402"
C34 C36 C57 C58 C59 C63 C65: library part CMP-0006325-2, "CAP, CERM, 0.1 uF, 50 V, +/- 10%, X7R, AEC-Q200 Grade 1, 0402"
C37 C38 C40 C41 C43: library part CMP-0078241-1, "CAP, CERM, 0.1 µF, 10 V,+/- 10%, X7R, 0402"
C39 C42: library part CMP-0006361-2, "CAP, CERM, 4700 pF, 50 V, +/- 10%, X7R, AEC-Q200 Grade 1, 0402"
C44 C45 C48 C49 C50 C52 C53: library part CMP-0086440-1, "Cap Ceramic 0.1uF 35V X5R 10% Pad SMD 0201 85C T/R"
C46 C47 C72 C73 C74 C75: library part CMP-0006339-4, "CAP, CERM, 10 uF, 10 V, +/- 20%, X5R, 0402"
C51: library part CMP-0086446-1, "1µF ±20% 16V Ceramic Capacitor X5R 0201"
C54 C55 C56 C60: library part CMP-0086438-1, "CAP CER 390PF 25V C0G/NP0 0201"
C61 C62 C66 C67 C90 C91 C98 C99 C100 C101 C102 C103 C104: library part CMP-0086447-1, "CAP CER 22UF 6.3V X5R 0402"
C68: library part CMP-0009781-1, "CAP, CERM, 0.22 uF, 10 V, +/- 20%, X5R, 0201"
C69: library part CMP-0007111-4, "CAP, CERM, 1 uF, 6.3 V, +/- 10%, X7R, 0603"
C70: library part CMP-0006858-4, "CAP, CERM, 0.1 uF, 50 V, +/- 5%, X7R, 0603"
C71: library part CMP-0006332-2, "CAP, CERM, 1000 pF, 100 V, +/- 10%, X7S, AEC-Q200 Grade 1, 0402"
C76 C78 C80 C82: library part CMP-0009174-2, "CAP, CERM, 22 uF, 16 V, +/- 10%, X7R, 1210"
C77 C79 C81 C83: library part CMP-0008017-2, "CAP, CERM, 10 uF, 10 V, +/- 10%, X7R, 0805"
C84 C92: library part CMP-0064967-2, "CAP, CERM, 0.47 uF, 10 V,+/- 10%, X7S, 0402"
C85 C89 C94: library part CMP-0006262-2, "CAP, CERM, 0.22 uF, 10 V, +/- 10%, X7R, 0402"
C86 C87 C88 C95 C96 C97: library part CMP-0007497-5, "CAP, CERM, 10 uF, 10 V, +/- 10%, X5R, 0603"
C93: library part CMP-0006272-2, "CAP, CERM, 1 uF, 10 V, +/- 10%, X6S, 0402"
"CAUTION HOT SURFACE1": library part CMP-0074837-1, "IEC 61010-1 Hot Surface Warning"
D1 D2: library part CMP-0028829-2, "Diode, Schottky, 30 V, 2 A, 2-XFDFN"
D3: library part CMP-0078196-2, "LED, Yellow, SMD"
D4 D5 D6 D7: library part CMP-0067682-2, "LED, Green, SMD"
FID1 FID2 FID3 FID4 FID5 FID6: library part CMP-0077181-1, "Fiducial mark.  There is nothing to buy or mount."
J1 J2 J6: library part CMP-0075524-1, "Receptacle, 0.5 mm, 30x2, Gold, TH"
J3 J4: library part CMP-0087785-1, "CONN HEADER R/A 3POS 1.27MM"
J5: library part CMP-0055293-1, "Connector, Receptacle, Micro-USB Type B, R/A, Bottom Mount SMT"
L1 L2 L3 L7: library part CMP-0003427-2, "Ferrite Bead, 100 ohm @ 100 MHz, 4 A, 0805"
L4 L5 L6 L8: library part CMP-0087178-1, "FIXED IND 470NH 4.5A 39 MOHM SMD"
L9 L10 L11 L12: library part CMP-0078934-1, "Inductor, Ferrite Bead, Ferrite, 2.2 A, 0.035 ohm, AEC-Q200 Grade 1, SMD"
LBL1: library part CMP-0003625-1, "Thermal Transfer Printable Labels, 0.650\" W x 0.200\" H - 10,000 per roll"
Logo1 Logo5: library part CMP-0074838-1, "Texas Instrument Corporate Signature"
Logo2: library part CMP-0074844-1
LOGO3: library part CMP-0074847-1, "FCC_disclaimer"
Logo4: library part CMP-0074769-1
Q1: library part CMP-0087176-1, "MOSFET N-CH 100V 170MA SOT23-3"
Q2: library part CMP-0000947-2, "MOSFET, N-CH, 100 V, 0.17 A, SOT-23"
R1 R195: library part CMP-0025884-3, "RES, 0, 5%, 0.125 W, 0603"
R2 R14 R44 R49 R52 R53 R54 R70 R71 R83 R84 R88 R94 R101 R103 R104 R105 R106 R107 R112 R113 R114 R115 R116 R117 R139 R142 R145 R146 R147 R152 R157 R158 R161 R162 R203 R206 R209: library part CMP-0025958-3, "RES, 10.0 k, 1%, 0.063 W, AEC-Q200 Grade 0, 0402"
R3 R43 R72 R73 R74 R75 R76 R77 R78 R80 R85 R87 R122 R202 R216: library part CMP-0026992-3, "RES, 0, 5%, 0.1 W, AEC-Q200 Grade 0, 0402"
R4 R5 R6 R7 R8 R9 R10 R11 R12 R13 R16 R22 R24 R25 R29 R30 R31 R32 R33 R34 R35 R36 R37 R38 R39 R40 R41 R42 R55 R56 R58 R59 R60 R61 R62 R63 R64 R65 R66 R67 R69 R82 R108 R109 R110 R111 R131 R133 R134 R135 R136 R137 R140 R143 R144 R159 R160 R217 R218 R219 R220 R221 R222 R223 R224 R225 R226 R227 R228 R229 R230: library part CMP-0027008-4, "RES, 0, 5%, 0.05 W, 0201"
R15 R17 R18 R19 R20 R21 R23 R26 R27 R28 R124 R125 R126 R127 R128 R129 R130 R132 R148 R149 R163 R164 R166 R167 R168 R170: library part CMP-0078192-2, "RES, 20.0, 1%, 0.05 W, 0201"
R45 R46 R47 R48 R51: library part CMP-0027275-3, "RES, 33.2, 1%, 0.05 W, 0201"
R50: library part CMP-0026395-2, "RES, 47.5 k, 1%, 0.063 W, AEC-Q200 Grade 0, 0402"
R57 R151 R185: library part CMP-0026822-3, "RES, 0, 5%, 0.063 W, AEC-Q200 Grade 0, 0402"
R68 R79 R81 R86: library part CMP-0026491-2, "RES, 61.9, 1%, 0.063 W, AEC-Q200 Grade 0, 0402"
R89: library part CMP-0026938-5, "RES, 4.7 k, 5%, 0.063 W, AEC-Q200 Grade 0, 0402"
R90 R93 R176 R177 R187 R188: library part CMP-0027745-1, "RES, 4.99 k, 1%, 0.05 W, 0201"
R91 R92 R96 R97 R98 R180 R181 R198 R214: library part CMP-0086442-2, "RES SMD 0 OHM JUMPER 1/20W 0201"
R95 R100 R102 R123 R138 R165 R189 R190 R215: library part CMP-0088002-1, "10 kOhms ±0.5% 0.05W, 1/20W Chip Resistor 0201 (0603 Metric)  Thin Film"
R99 R212 R213: library part CMP-0027072-1, "RES, 220, 5%, 0.05 W, 0201"
R118 R141 R171 R174: library part CMP-0027137-1, "RES, 510, 5%, 0.05 W, 0201"
R119 R120 R201: library part CMP-0027261-3, "RES, 100 k, 1%, 0.05 W, 0201"
R121: library part CMP-0087183-1, "RES SMD 200 OHM 1% 1/5W 0402"
R150 R169 R184: library part CMP-0026825-5, "RES, 10 k, 5%, 0.063 W, AEC-Q200 Grade 0, 0402"
R153 R154 R155 R156 R182: library part CMP-0025950-3, "RES, 100 k, 1%, 0.063 W, AEC-Q200 Grade 0, 0402"
R172 R179: library part CMP-0078212-1, "RES, 510, 5%, 0.1 W, AEC-Q200 Grade 0, 0402"
R173 R175 R178 R183: library part CMP-0086444-2, "RES Thick Film SMD 3.83O 1% 1/16W 0402 200ppm/°C"
R186: library part CMP-0027052-1, "RES, 1.0 k, 5%, 0.05 W, 0201"
R191: library part CMP-0081973-1, "RES, 0, 0%, 0.25 W, AEC-Q200 Grade 0, 0603"
R192 R193 R199 R200: library part CMP-0081623-1, "RES, 0.002, 1%, 1 W, AEC-Q200 Grade 0, 1206"
R194: library part CMP-0027452-1, "RES, 1.96 k, 1%, 0.05 W, 0201"
R196: library part CMP-0026944-3, "RES, 510, 5%, 0.063 W, AEC-Q200 Grade 0, 0402"
R197: library part CMP-0026659-1, "RES, 100 k, 1%, 0.1 W, 0402"
R204 R207 R210: library part CMP-0026557-2, "RES, 7.87 k, 1%, 0.063 W, AEC-Q200 Grade 0, 0402"
R205 R208 R211: library part CMP-0026574-2, "RES, 82.5 k, 1%, 0.063 W, AEC-Q200 Grade 0, 0402"
S1: library part CMP-0002304-1, "Switch, SPST, Slide, Off-On, 6 Pos, 0.025A, 24V, SMD"
S2 S3: library part CMP-0002150-2, "SWITCH TACTILE SPST-NO 0.05A 12V"
TP1 TP8 TP9 TP10 TP11: library part CMP-0078143-3, "TEST POINT.  No entry in BOM."
TP2 TP3 TP4 TP5 TP6 TP7: library part CMP-0003825-1, "1mm Test Point, SMT"
TP12 TP13 TP14: library part CMP-0055138-1, "Test Point, Miniature, Black, TH"
U1: library part CMP-0081105-1, "IWR1843QAGABL, ABL0161B (FCBGA-161)"
U2: library part CMP-0079267-1, "2.3V-3.6V, 16M-BIT [x 1/x 2/x 4] CMOS FLASH Memory, WSON-8"
U3: library part CMP-0067398-2, "Automotive Grade, 1.4V-Capable +/-0.5degC Temperature Sensor with Alert Function and I2C/SMBus, DRL0006A (SOT-OTHER-6)"
U4: library part CMP-0079120-2, "4-A + 2.5-A + Two 1.5-A Buck Converters With Integrated Switches, RNF0026C (VQFN-HR-26)"
U5 U12: library part CMP-0075992-1, "Automotive Fault Protected CAN Transceiver With Flexible Data-Rate, D0008A (SOIC-8)"
U6 U7 U8 U10: library part CMP-0037978-1, "High-Side Measurement, Bi-Directional Current / Power Monitor with I2C Interface, 2.7 to 5.5 V, -40 to 125 degC, 10-pin SOP (DGS10), Green (RoHS & no Sb/Br)"
U9: library part CMP-0077265-1, "5.5-V, 2-A, 80 mohm Low Leakage Load Switch with RCB and Programmable Rise Time, DBV0006A (SOT-23-6)"
U11: library part CMP-0005309-2, "IC, EEPROM, 8KBIT, 400KHZ, 8SOIC"
U13: library part CMP-0067415-1, "10-Ohm Quad SPDT Analog Switch, RSV0016A (UQFN-16)"
U14: library part CMP-0087172-1, "I/O Controller Interface IC USB to Dual UART bridge"
U15: library part CMP-0074545-1, "Dual 10-ohm SPDT Analog Switch, RSE0010A (UQFN-10)"
U16: library part CMP-0043358-3, "Dual In / Single Out Autoswitching Power Mux, 2.8 to 5.5 V, -40 to 85 degC, 8-pin SON (DRB), Green (RoHS & no Sb/Br)"
U17: library part CMP-0051215-4, "Single 3-Input Positive-AND Gate, DSF0006A, LARGE T&R"
Y1: library part CMP-0004694-3, "Crystal, 40 MHz, 8pF, SMD"
ZZ1: library part CMP-0003616-3
ZZ2: library part CMP-0077236-1
ZZ3: library part CMP-0077237-1
ZZ4 ZZ5: library part CMP-0077238-1

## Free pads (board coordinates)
  round 157.48 hole 118.11: TH1(118.11,2248.99) TH2(118.11,1406.24) TH3(118.11,1087.57) TH4(118.11,339.54) TH5(2047.24,339.54) TH6(2047.24,1087.57) TH7(2047.24,1406.24) TH8(2047.24,2248.99)
  round 140 hole 80: TH9(576.76,1331.62)

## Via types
v1: diameter 15.74, hole 5.9, Top Layer to L2_GND, tented both sides, 900 vias
v2: diameter 22.4, hole 12.2, Top Layer to Bottom Layer, tented both sides, 509 vias
v3: diameter 15.75, hole 5.9, Top Layer to L2_GND, tented both sides, 72 vias
v4: diameter 18, hole 8, Top Layer to Bottom Layer, tented both sides, 71 vias
v5: diameter 22, hole 12.2, Top Layer to Bottom Layer, tented both sides, 57 vias
v6: diameter 25, hole 15, Top Layer to Bottom Layer, tented both sides, 28 vias
v7: diameter 19.68, hole 7.87, Top Layer to Bottom Layer, 16 vias
v8: diameter 15.74, hole 5.9, Top Layer to L2_GND, tented top, 15 vias
v9: diameter 15.75, hole 5.9, Top Layer to L2_GND, tented top, 1 vias

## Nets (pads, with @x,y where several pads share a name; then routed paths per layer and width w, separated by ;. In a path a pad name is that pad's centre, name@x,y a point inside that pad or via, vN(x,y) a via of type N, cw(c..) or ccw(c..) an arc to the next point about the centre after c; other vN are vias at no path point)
5V_IN: C68.1 C72.1 C73.1 C74.1 C75.1 D2.1 R69.2 R82.2 R90.1 R141.1 R174.1 R186.2 U4.9 U4.13 U4.18 U4.22 U4.26 | length 364.5
  Top Layer w9.84: R141.1@302.97,1116.87 308.78,1122.68 v2(308.78,1138.39)
  Top Layer w10: C75.1@950.83,200.89 950.83,223.3 960.96,233.43 U4.9@960.96,265.51 ; C74.1@950.83,451.39 950.83,428.98 960.96,418.85 U4.26@960.96,386.77 ; U4.13@1039.7,265.51 1039.7,233.43 1049.83,223.3 C73.1@1049.83,202.29 ; U4.22@1039.7,386.77 1039.7,418.85 1049.83,428.98 C72.1@1049.83,451.39
  Bottom Layer w15: v2(201.99,84.5) R82.2@201.99,129.09 ; R69.2@330.22,335.07 330.22,315.24 330.53,314.94 v2(332.34,314.94)
  other v2: 679.79,-258.11 679.82,-228.33 662.96,-183.19 610.5,-182.91 713.35,-131.1 165.35,111.32 1809.17,120.91 1849.47,124.48 162.78,152.06 1809.17,157.47 1849.29,159.53 1849.85,192.89 1809.17,193.14 1300.3,250.04 1329.54,255.23 1297.59,277.62 1335.18,280.54 1300.97,306.11 1333.95,307.04
  other v4: 920.36,194.17 1080.5,194.84 934.22,209.76 1066.79,210.64 1134.94,339.66 932.29,441.44 1067.6,443.6 921.03,458.3 1081.97,458.12
  other v6: 1778.08,240.49 1751.96,262.51 1801.21,265.47
5V_IN_SW: C51.1 L10.1 R118.1 U16.7 | length 31.9
  Top Layer w10: R118.1@1532.37,316.41 1539.45,309.33 v5(1561.35,309.33)
  other v2: 1650.14,244.33 1684.05,244.33 1672.31,276.25
5V_IN_USB: C46.2 C47.1 C49.1 C84.1 C85.1 D1.1 U16.6
  other v2: 1843.58,-265.3 1880.99,-265.09 1808.82,-264.07 1686.66,-262.97 1728.5,-262.8 1770.35,-262.5 1876.23,-234.87 1686.58,-227.4 1720.32,-227.18 1753.28,-226.14 1899.27,-208.38 1667.59,151.02 1707.59,157.78 1683.82,175.18 1655.26,177.05 1707.48,189.96 1675.7,203.99
A2: R161.1 R162.2 U11.3 | length 107.2
  Bottom Layer w6: U11.3@782.28,2026.43 840.32,2026.43 R161.1@850.32,2016.43 R162.2@850.32,1981.43
CAN1_RX: R80.1 U13.3 | length 105.5
  Top Layer w6: R80.1@538.88,257.94 563.02,257.94 590.27,285.18 611.78,285.18 616.24,280.73 U13.3@631.29,280.73
CAN1_TX: R78.1 U13.16 | length 172.4
  Top Layer w6: v2(579,337.48) 589.12,347.6 632.4,347.6 639.17,340.83 U13.16@639.17,335.85
  Bottom Layer w6: R78.1@528.88,257.94 554.72,283.79 554.72,313.2 v2(579,337.48)
CAN2_RX: R87.1 U13.9 | length 418.2
  Top Layer w6: R87.1@428.19,205.08 432.81,205.08 460.79,177.09 488.01,177.09 496.59,185.67 714.88,185.67 738.12,208.92 738.12,237.03 710.16,264.98 U13.9@694.28,264.98
CAN2_TX: R85.1 U13.12 | length 696.7
  Top Layer w6: R85.1@428.19,60.08 382.63,105.63 382.63,115.21 379.88,117.96 379.88,150.27 402.73,173.12 442.28,173.12 449.31,166.09 497.27,166.09 504.85,173.67 722.05,173.67 750.12,201.74 750.12,320.63 737.01,333.74 720.28,333.74 698.77,312.23 U13.12@694.28,312.23
CB_PMIC_1V0: C2.2 C3.2 J1.1 J1.3 L2.1 L3.1 R199.2 U7.9
  other v5: 1536.92,518.37 1657.89,518.6
  other v6: 445.8,1420.92 499.8,1436.09 446.03,1474.24 447.08,1520.63 489.76,1551.39 530.74,1576.08 728.76,1765.72 729.8,1801.55 687.8,1803.74 730.31,1832.57
CB_PMIC_1V2: C64.2 J1.5 J1.7 L7.1 R193.2 U8.9
  other v2: 819.72,228.41 784.61,235.94 819.27,258.44 785.5,267.46
  other v5: 531.47,1802.62 585.75,1847.06 617.61,1895.02 584.71,1940.63
CB_PMIC_1V8: C1.2 J1.9 L1.1 R192.2 R195.1 U6.9 | length 200.6
  Top Layer w10: U6.9@1323.04,374.27 1323.04,443.54 1411.63,532.13 R192.2@1417.66,532.13
  other v2: 1011.21,725.57 1030.65,748.13 993.86,758.33 1037.39,775.84 1008.64,781.2
  other v5: 1661.2,561.4 1678.37,579.14 1660.79,597.45
CONN_5V: C50.1 C92.1 C93.1 C94.1 C95.2 C96.2 C97.2 J1.2 J2.58 J2.59 J2.60 R102.1 R122.1 TP13.1 U16.8 | length 163.2
  Top Layer w25: v2(256.29,1127.59) 256.29,1107.32 259.45,1104.16 v2@277.2,1104.16 ; v2(666.86,-28.08) 666.86,-40.06 674.81,-48.01 v2(674.81,-72.03)
  Bottom Layer w15: v2@1092.45,-51.23 v2(1092.45,-27.49) ; v5(1385.91,229.68) v5@1385.91,253.61
  Bottom Layer w20: v2(1563.64,-41.98) 1567.5,-38.13 1567.5,-19.83 v2(1568.93,-18.4)
  other v2: 1091.96,-51.23 675,-49.36 256.29,1104.77 278.68,1104.16
  other v5: 1386.72,253.61
  other v6: 1719.16,383.04 1676.81,384.36 1758.2,385.29 1635.07,388.55 1809.94,482.31 1845.11,483.32
CONN_RS232RX: J6.55 R38.1 U15.7 | length 1968.5
  Top Layer w6: v2(1864.93,244.44) 1872.92,252.43 U15.7@1872.92,275.06
  L4_SIGNAL 2 w6: v5(1722.15,1195.52) 1722.15,1149.74 1710.89,1138.48 1710.89,1079.09 1741.74,1048.24 1770.68,1048.24 1823.59,995.33 1823.59,622.17 1927.74,518.02 1927.74,489.66 1954.21,463.19 1954.21,417.25 1926.5,389.55 1926.5,373.49 1864.93,311.92 v2(1864.93,244.44)
  Bottom Layer w6: J6.55@1465.8,34.94 1465.8,85.98 1478.49,98.66 1485.21,98.66 1490.06,103.52 1527.19,103.52 1537.16,93.55 1570.81,93.55 1607.64,56.71 1625.01,56.71 1670.38,11.35 1670.38,2.23 1687.3,-14.7 1831.81,-14.7 1884.25,37.75 1884.25,225.11 v2(1864.93,244.44) ; R38.1@1717.94,1250.43 1722.15,1246.21 v5(1722.15,1195.52)
CONN_RS232TX: J6.57 R40.1 U15.9 | length 2076.2
  Top Layer w6: U15.9@1912.29,275.06 1912.29,270.37 1915.45,267.21 1928.59,267.21 v2(1933.67,262.13)
  L4_SIGNAL 2 w6: v5(1749.67,1214.36) 1749.67,1191.86 1741.16,1183.36 1741.16,1151.79 1723.92,1134.54 1723.92,1083.03 1746.71,1060.24 1775.65,1060.24 1842.84,993.05 1842.84,654.37 1875.84,621.37 1892.62,621.37 1907.45,606.55 1907.45,562.06 1939.49,530.02 1939.49,496.37 1970.84,465.02 1970.84,418.32 1937.5,384.99 1937.5,360.66 1906.89,330.04 1906.89,288.91 v2(1933.67,262.13)
  Bottom Layer w6: J6.57@1485.49,34.94 1485.49,81.97 1495.03,91.52 1522.21,91.52 1532.19,81.55 1565.84,81.55 1602.67,44.71 1621.45,44.71 1658.38,7.79 1658.38,-36 1678.69,-56.31 1805.75,-56.31 1903.09,41.03 1903.09,165.53 1933.67,196.11 v2(1933.67,262.13) ; R40.1@1717.94,1288.81 1749.67,1257.08 v5(1749.67,1214.36)
EN_3V3: R195.2 R197.2 U9.3 | length 146.7
  Top Layer w10: v2(871.83,863) 871.83,832.06 871.6,831.84 U9.3@876.14,827.3 876.14,775.19 R195.2@893.75,757.58
  Bottom Layer w10: v2(871.83,863) 871.83,832.42 871.6,832.19 R197.2@872.36,831.43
